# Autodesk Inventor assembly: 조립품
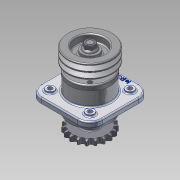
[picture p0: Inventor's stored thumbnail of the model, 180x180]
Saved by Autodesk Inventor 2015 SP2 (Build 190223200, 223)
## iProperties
Created: 2015-07
Part Number: 조립품
Document SubType Name: Assembly
Designer: AMC
Author: AMC
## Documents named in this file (12)
- C:\Users\AMC\Desktop\450735V1011\조립품.iam
- C:\Users\AMC\Desktop\450735V1011\본체.ipt
- C:\Users\AMC\Desktop\450735V1011\2-커버.ipt
- C:\Users\AMC\Desktop\450735V1011\3-축.ipt
- C:\Users\AMC\Desktop\450735V1011\4-V벨트풀리.ipt
- C:\Users\AMC\Desktop\450735V1011\5-체인 스프로킷.ipt
- C:\Users\AMC\Desktop\450735V1011\6-베어링 6206.ipt
- C:\Users\AMC\Desktop\450735V1011\7-부시.ipt
- C:\Users\AMC\Desktop\450735V1011\8-오일실 30x42.ipt
- C:\Users\AMC\Desktop\450735V1011\9-M16-너트.ipt
- C:\Users\AMC\Desktop\450735V1011\10-M6.ipt
- C:\Users\AMC\Desktop\450735V1011\11-키 6x6.ipt
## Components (16 placed, 10 different names)
1. 2-커버:1
2. 3-축:1
3. 4-V벨트풀리:1 — 각도:1
4. 5-체인 스프로킷:1 — 각도:2
5. 6-베어링 6206:1
6. 7-부시:1
7. 8-8-오일실 30x42:1
8. 9-M16 너트:1
9. 10-M6:1
10. 11-키 6x6:1 — 각도:1
11. 6-베어링 6206:2
12. 8-8-오일실 30x42:2
13. 2-커버:2
14. 9-M16 너트:2
15. 10-M6:2
16. 11-키 6x6:2 — 각도:2
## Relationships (2: Angle 2)
- 각도:1 [Angle]: 4-V벨트풀리:1 ↔ 11-키 6x6:1
- 각도:2 [Angle]: 5-체인 스프로킷:1 ↔ 11-키 6x6:2
